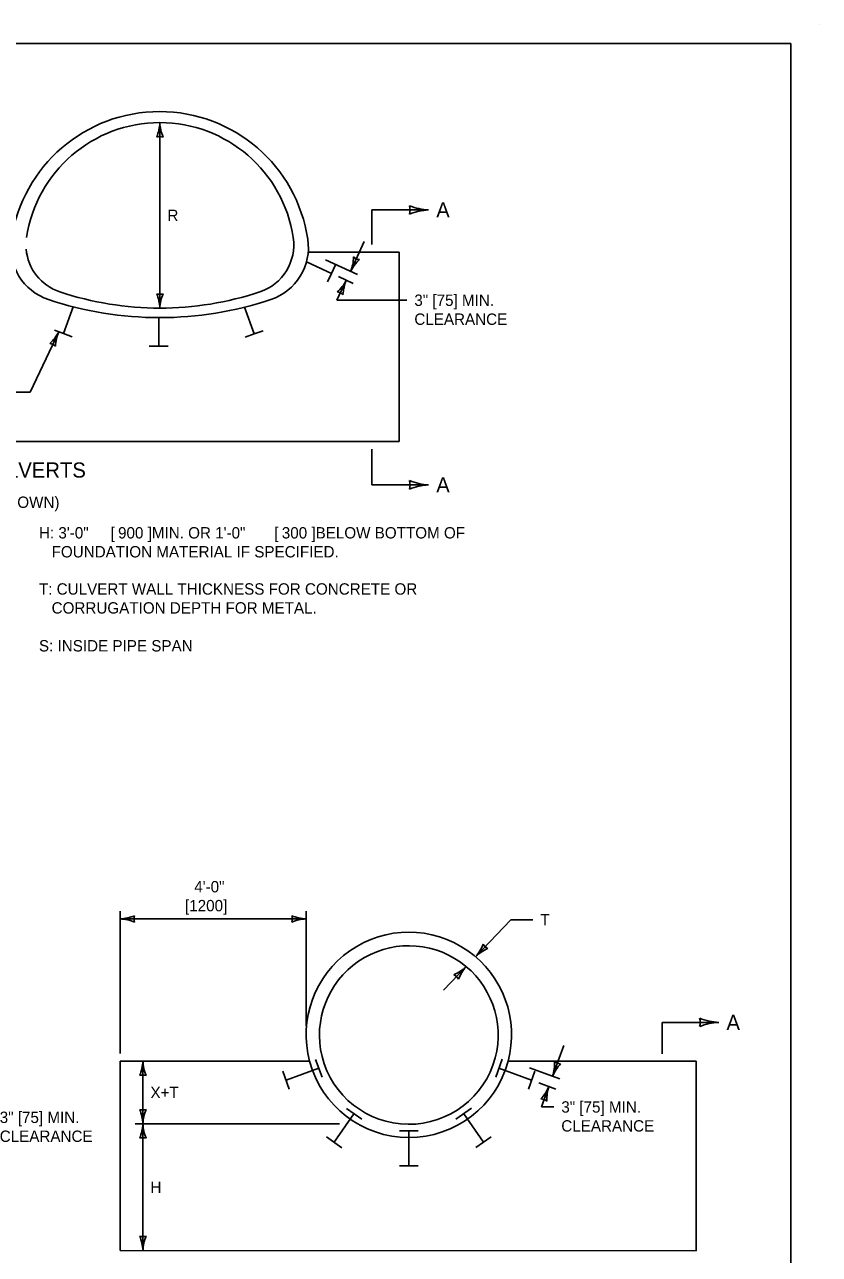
# Model space of a CAD drawing. Extents: x 49988.5 to 50021, y 49987.6 to 50011.4.
# Drawn here: x 50004.57 to 50008.76, y 50004.87 to 50011.36 of the extents above; entities that cross this region are included whole.
import ezdxf

# ---------------------------------------------------------------- set-up
doc = ezdxf.new("R2010")
doc.units = 0
for name, color, linetype in [('Level 1', 7, 'Continuous'), ('Level 2', 7, 'Continuous'), ('Level 3', 7, 'Continuous'), ('Level 6', 7, 'Continuous')]:
    doc.layers.add(name, color=color, linetype=linetype)

msp = doc.modelspace()

# ---------------------------------------------------------------- linework, layer by layer
at = {"layer": 'Level 1'}
for p, q in [((50008.7646, 50011.3628), (50008.7646, 50011.3628)), ((50006.0658, 50010.1613), (50006.5462, 50010.1613)), ((50006.5462, 50010.1613), (50006.5462, 50009.1613)), ((50006.1888, 50010.0494), (50006.0569, 50010.1111)), ((50006.1888, 50010.0494), (50006.21, 50010.0948)), ((50006.21, 50010.0948), (50006.1888, 50010.0494)), ((50006.1679, 50010.0042), (50006.1888, 50010.0494)), ((50004.7735, 50009.7321), (50004.8247, 50009.8729)), ((50005.277, 50009.6658), (50005.277, 50009.8158)), ((50005.7807, 50009.7298), (50005.7295, 50009.8707)), ((50004.7264, 50009.7492), (50004.7735, 50009.7321)), ((50005.7807, 50009.7298), (50005.8278, 50009.7468)), ((50004.7735, 50009.7321), (50004.8204, 50009.715)), ((50005.7338, 50009.7126), (50005.7807, 50009.7298)), ((50005.227, 50009.6658), (50005.277, 50009.6658)), ((50005.277, 50009.6658), (50005.327, 50009.6658)), ((50001.9329, 50009.1613), (50006.5462, 50009.1613)), ((50005.073, 50005.8907), (50005.073, 50004.8907)), ((50005.073, 50005.8907), (50006.0732, 50005.8907)), ((50005.949, 50005.7899), (50006.1215, 50005.8539)), ((50006.1389, 50005.8059), (50006.1048, 50005.8998)), ((50007.0557, 50005.8068), (50007.0902, 50005.9005)), ((50007.2454, 50005.7899), (50007.073, 50005.8538)), ((50007.121, 50005.8897), (50008.1146, 50005.8897)), ((50008.1146, 50005.8897), (50008.1146, 50004.8897)), ((50005.966, 50005.7431), (50005.9319, 50005.837)), ((50007.2282, 50005.7432), (50007.2627, 50005.8369)), ((50006.2028, 50005.4622), (50006.3076, 50005.6131)), ((50006.3491, 50005.584), (50006.2674, 50005.6413)), ((50006.846, 50005.5847), (50006.9279, 50005.6416)), ((50006.9916, 50005.4622), (50006.8868, 50005.6131)), ((50006.2436, 50005.4336), (50006.1619, 50005.4909)), ((50006.5472, 50005.5222), (50006.6472, 50005.5222)), ((50006.5972, 50005.3373), (50006.5972, 50005.5222)), ((50006.9507, 50005.4338), (50007.0326, 50005.4907)), ((50006.5472, 50005.3373), (50006.6472, 50005.3373)), ((50008.1146, 50004.8897), (50005.073, 50004.8907))]:
    msp.add_line(p, q, dxfattribs=at)
msp.add_lwpolyline([(50008.6146, 50011.2628), (50000.3356, 50011.2628), (50000.3356, 50000.0624), (50008.6146, 50000.0624)], close=True, dxfattribs=at)
for centre, radius, start, end in [((50005.2815, 50010.1128), 0.7909, 8.49352, 171.50648), ((50005.2828, 50010.1334), 0.7118, 8.49352, 171.50648), ((50004.7867, 50010.1867), 0.2906, 171.50648, 251.56311), ((50005.7281, 50010.1999), 0.2615, 288.43689, 8.49352), ((50005.7763, 50010.1867), 0.2906, 288.43689, 8.49352), ((50004.8375, 50010.1999), 0.2615, 185.01218, 251.56311), ((50005.2828, 50011.5357), 1.6696, 251.5631, 288.43689), ((50005.2815, 50011.6709), 1.8551, 251.5631, 288.43689), ((50006.5972, 50006.0294), 0.5421, 345.07164, 194.92937), ((50006.5972, 50006.0279), 0.4718, 345.24996, 193.78371), ((50006.5972, 50006.0294), 0.4721, 193.96469, 345.06898), ((50006.5972, 50006.0294), 0.5421, 194.92937, 345.07164)]:
    msp.add_arc(centre, radius, start, end, dxfattribs=at)
at = {"layer": 'Level 3'}
for p, q in [((50005.2828, 50009.8661), (50005.2828, 50010.8452)), ((50006.3618, 50010.2173), (50006.2891, 50010.0598)), ((50006.3254, 50010.0429), (50006.1577, 50010.1213)), ((50006.217, 50009.9076), (50006.2669, 50010.0129)), ((50006.3031, 50009.996), (50006.225, 50010.0325)), ((50006.217, 50009.9076), (50006.5862, 50009.9076)), ((50004.749, 50009.741), (50004.5977, 50009.4215)), ((50004.5977, 50009.4215), (50004.4234, 50009.4215)), ((50005.073, 50005.9307), (50005.073, 50006.6815)), ((50005.073, 50006.6415), (50006.0552, 50006.6415)), ((50006.0552, 50006.0761), (50006.0552, 50006.6815)), ((50006.9493, 50006.4416), (50007.1361, 50006.6367)), ((50007.1361, 50006.6367), (50007.251, 50006.6367)), ((50006.8997, 50006.3899), (50006.7798, 50006.2645)), ((50007.3563, 50005.811), (50007.4158, 50005.9739)), ((50005.1932, 50005.5596), (50005.1932, 50005.8907)), ((50007.2348, 50005.8554), (50007.3939, 50005.7973)), ((50007.283, 50005.7763), (50007.374, 50005.7431)), ((50007.3364, 50005.7567), (50007.2969, 50005.6487)), ((50007.2969, 50005.6487), (50007.3621, 50005.6487)), ((50006.2305, 50005.5596), (50005.1532, 50005.5596)), ((50005.1932, 50005.5596), (50005.1932, 50004.8907))]:
    msp.add_line(p, q, dxfattribs=at)
for centre, radius, start, end in [((50005.0607, 50010.8543), 0.2223, 337.45601, 357.63952), ((50005.5155, 50010.8566), 0.233, 182.82731, 202.07716), ((50005.2828, 50010.7169), 0.0548, 72.13882, 107.86118), ((50006.0836, 50010.1445), 0.2223, 337.5968, 357.78031), ((50006.3428, 50010.1762), 0.0548, 227.37514, 263.0975), ((50006.4956, 50009.9519), 0.233, 133.15916, 152.40901), ((50006.0701, 50010.1163), 0.2223, 312.09816, 332.28167), ((50006.4821, 50009.9236), 0.233, 157.46946, 176.71931), ((50005.2828, 50009.9943), 0.0548, 252.13882, 287.86118), ((50005.0501, 50009.8546), 0.233, 2.82731, 22.07716), ((50005.5049, 50009.8569), 0.2223, 157.45601, 177.63952), ((50006.212, 50009.897), 0.0548, 46.78097, 82.50333), ((50004.5522, 50009.8444), 0.2223, 312.10823, 332.29174), ((50004.6942, 50009.6251), 0.0548, 46.79104, 82.5134), ((50004.9643, 50009.6517), 0.233, 157.47953, 176.72938), ((50005.0615, 50006.8742), 0.233, 272.82731, 292.07716), ((50005.0638, 50006.4194), 0.2223, 67.45601, 87.63952), ((50005.2012, 50006.6415), 0.0548, 162.13882, 197.86118), ((50006.0644, 50006.8637), 0.2223, 247.45601, 267.63952), ((50005.927, 50006.6415), 0.0548, 342.13882, 17.86118), ((50006.0667, 50006.4088), 0.233, 92.82731, 112.07716), ((50006.7732, 50006.5942), 0.233, 319.07466, 338.32451), ((50007.0379, 50006.5342), 0.0548, 208.38617, 244.10853), ((50007.1034, 50006.2814), 0.2223, 113.70336, 133.88687), ((50006.7456, 50006.5501), 0.2223, 293.70336, 313.88687), ((50007.0758, 50006.2372), 0.233, 139.07466, 158.32451), ((50006.8111, 50006.2972), 0.0548, 28.38617, 64.10853), ((50004.9711, 50005.8999), 0.2223, 337.45601, 357.63952), ((50005.4259, 50005.9022), 0.233, 182.82731, 202.07716), ((50007.1338, 50005.8801), 0.233, 342.75579, 2.00564), ((50007.5618, 50005.7262), 0.2223, 137.38449, 157.56799), ((50007.4003, 50005.9314), 0.0548, 232.06729, 267.78966), ((50005.1932, 50005.7625), 0.0548, 72.13882, 107.86118), ((50007.1309, 50005.8416), 0.2223, 317.37296, 337.55647), ((50007.5589, 50005.6876), 0.233, 162.74426, 181.99411), ((50007.2923, 50005.6363), 0.0548, 52.05577, 87.77813), ((50005.1932, 50005.6879), 0.0548, 252.13882, 287.86118), ((50004.9605, 50005.5481), 0.233, 2.82731, 22.07716), ((50005.4153, 50005.5505), 0.2223, 157.45601, 177.63952), ((50004.9711, 50005.5688), 0.2223, 337.45601, 357.63952), ((50005.4259, 50005.5711), 0.233, 182.82731, 202.07716), ((50005.1932, 50005.4314), 0.0548, 72.13882, 107.86118), ((50005.1932, 50005.0189), 0.0548, 252.13882, 287.86118), ((50004.9605, 50004.8792), 0.233, 2.82731, 22.07716), ((50005.4153, 50004.8815), 0.2223, 157.45601, 177.63952)]:
    msp.add_arc(centre, radius, start, end, dxfattribs=at)
at = {"layer": 'Level 6'}
for p, q in [((50006.7018, 50010.3844), (50006.4018, 50010.3844)), ((50006.4018, 50010.3844), (50006.4018, 50010.2013)), ((50006.4018, 50009.1213), (50006.4018, 50008.9329)), ((50006.4018, 50008.9329), (50006.7018, 50008.9329)), ((50008.234, 50006.0952), (50007.934, 50006.0952)), ((50007.934, 50006.0952), (50007.934, 50005.9297))]:
    msp.add_line(p, q, dxfattribs=at)
for centre, radius, start, end in [((50006.714, 50010.6806), 0.2964, 247.45601, 267.63952), ((50006.5308, 50010.3844), 0.073, 342.13882, 17.86118), ((50006.7171, 50010.0741), 0.3107, 92.82731, 112.07716), ((50006.714, 50009.2291), 0.2964, 247.45601, 267.63952), ((50006.5308, 50008.9329), 0.073, 342.13882, 17.86118), ((50006.7171, 50008.6226), 0.3107, 92.82731, 112.07716), ((50008.2462, 50006.3914), 0.2964, 247.45601, 267.63952), ((50008.063, 50006.0952), 0.073, 342.13882, 17.86118), ((50008.2493, 50005.785), 0.3107, 92.82731, 112.07716)]:
    msp.add_arc(centre, radius, start, end, dxfattribs=at)

# ---------------------------------------------------------------- texts
at = {"layer": 'Level 2'}
for s, height, p in [('A', 0.08, (50006.7418, 50010.3444)), ('R', 0.06, (50005.3228, 50010.3256)), ('3" [75] MIN.', 0.06, (50006.6262, 50009.8776)), ('CLEARANCE', 0.06, (50006.6262, 50009.7776)), ('MULTIPLE ARCH CULVERTS', 0.08, (50003.4357, 50008.9713)), ('A', 0.08, (50006.7418, 50008.8929)), ('(METAL CULVERTS SHOWN)', 0.06, (50003.6518, 50008.8113)), ('H: 3\'-0" ', 0.06, (50004.6445, 50008.6498)), ('[', 0.06, (50005.0224, 50008.6498)), ('900', 0.06, (50005.0621, 50008.6498)), (']', 0.06, (50005.2186, 50008.6498)), (' MIN. OR 1\'-0" ', 0.06, (50005.2182, 50008.6498)), ('[', 0.06, (50005.8868, 50008.6498)), ('300', 0.06, (50005.9265, 50008.6498)), (']', 0.06, (50006.083, 50008.6498)), (' BELOW BOTTOM OF', 0.06, (50006.0826, 50008.6498)), ('   FOUNDATION MATERIAL IF SPECIFIED.', 0.06, (50004.6445, 50008.5498)), ('T: CULVERT WALL THICKNESS FOR CONCRETE OR', 0.06, (50004.6445, 50008.3533)), ('   CORRUGATION DEPTH FOR METAL.', 0.06, (50004.6445, 50008.2533)), ('S: INSIDE PIPE SPAN', 0.06, (50004.6445, 50008.0533)), ('4\'-0"', 0.06, (50005.4643, 50006.7815)), ('[1200]', 0.06, (50005.4156, 50006.6815)), ('T', 0.06, (50007.291, 50006.6067)), ('A', 0.08, (50008.274, 50006.0552)), ('X+T', 0.06, (50005.2332, 50005.6951)), ('3" [75] MIN.', 0.06, (50007.4021, 50005.6187)), ('3" [75] MIN.', 0.06, (50004.4374, 50005.564)), ('CLEARANCE', 0.06, (50004.4374, 50005.464)), ('CLEARANCE', 0.06, (50007.4021, 50005.5187)), ('H', 0.06, (50005.2332, 50005.1951))]:
    msp.add_text(s, height=height, dxfattribs=at).set_placement(p)

doc.saveas('drawing.dxf')
